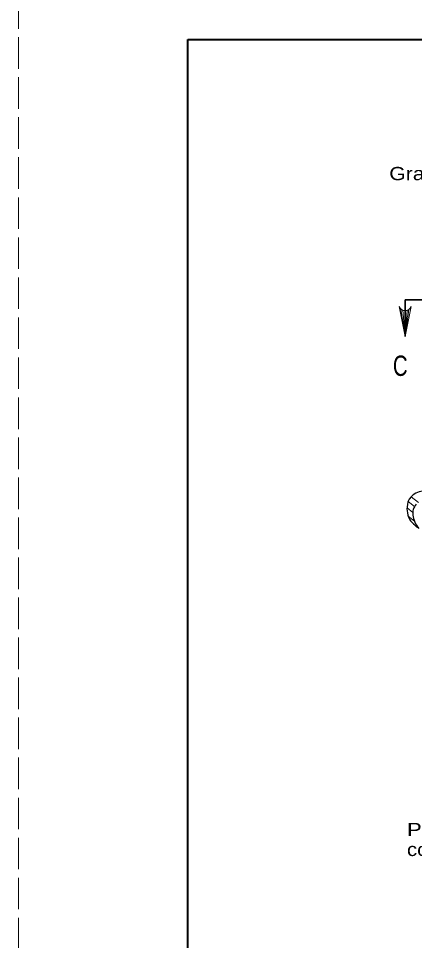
# Model space of a CAD drawing. Extents: x -410.5 to -376.5, y 1617.6 to 1661.6.
# Drawn here: x -410.45 to -405.78, y 1628.44 to 1639.31 of the extents above; entities that cross this region are included whole.
import ezdxf
from ezdxf.enums import TextEntityAlignment as Align

# ---------------------------------------------------------------- set-up
doc = ezdxf.new("R2010")
doc.units = 0
doc.header["$LTSCALE"] = 0.062
doc.linetypes.add('LONG_DASHED', pattern=[7.5, 6, -1.5])
doc.layers.add('1', color=7, linetype='Continuous', lineweight=13)

msp = doc.modelspace()

# ---------------------------------------------------------------- linework, layer by layer
at = {"layer": '1', "lineweight": 25}
msp.add_line((-408.45475, 1639.06183), (-376.95475, 1639.06183), dxfattribs=at)
at = {"layer": '1', "lineweight": 35}
for q in [(-400.21625, 1635.99217), (-405.888, 1635.5595)]:
    msp.add_line((-405.888, 1635.99217), q, dxfattribs=at)
at = {"layer": '1'}
for p, q in [((-405.93758, 1635.88375), (-405.888, 1635.5595)), ((-405.91683, 1635.8715), (-405.888, 1635.5595)), ((-405.84317, 1635.88), (-405.888, 1635.5595)), ((-405.86533, 1635.86908), (-405.888, 1635.5595)), ((-405.888, 1635.86583), (-405.888, 1635.5595)), ((-405.73167, 1633.60325), (-405.81658, 1633.67158)), ((-405.79842, 1633.48508), (-405.86592, 1633.53942)), ((-405.77842, 1633.55492), (-405.85283, 1633.61483)), ((-405.77775, 1633.38258), (-405.85083, 1633.44133)), ((-405.72758, 1633.29925), (-405.788, 1633.34783))]:
    msp.add_line(p, q, dxfattribs=at)
at = {"layer": '1', "linetype": 'LONG_DASHED'}
msp.add_lwpolyline([(-410.45475, 1617.56183), (-376.45475, 1617.56183), (-376.45475, 1639.56183), (-410.45475, 1639.56183)], close=True, dxfattribs=at)
at = {"layer": '1', "lineweight": 25}
msp.add_lwpolyline([(-376.95475, 1618.06183), (-408.45475, 1618.06183), (-408.45475, 1639.06183)], dxfattribs=at)
at = {"layer": '1', "lineweight": 40}
msp.add_lwpolyline([(-408.45475, 1639.06183), (-376.95475, 1639.06183), (-376.95475, 1618.06183), (-408.45475, 1618.06183)], close=True, dxfattribs=at)
msp.add_lwpolyline([(-408.45475, 1639.06183), (-376.95475, 1639.06183), (-376.95475, 1618.06183), (-408.45475, 1618.06183)], close=True, dxfattribs=at)
at = {"layer": '1'}
msp.add_lwpolyline([(-405.95883, 1635.9135), (-405.888, 1635.5595), (-405.81725, 1635.9135)], dxfattribs=at)
msp.add_arc((-405.88795, 1635.94207), 0.0764, 202.08605, 337.91218, dxfattribs=at)
at = {"layer": '1', "lineweight": 25}
for centre, major_axis, start_param, end_param in [((-405.63858, 1633.56188), (-0.22424, 0), 4.73259403, 6.19188747), ((-405.45475, 1633.53067), (-0.41142, 0), 6.13873376, 6.73878887), ((-405.58935, 1633.48317), (-0.20914, 0), 5.64753358, 6.45081579), ((-405.40132, 1633.4797), (0.39543, 0), 3.21902516, 3.74898168), ((-405.34174, 1633.65852), (0.59018, 0), 3.75535936, 4.00331106)]:
    msp.add_ellipse(centre, major_axis=major_axis, ratio=0.804622, start_param=start_param, end_param=end_param, dxfattribs=at)

# ---------------------------------------------------------------- texts
at = {"layer": '1'}
for s, width, p in [('Grate', 1.2, (-406.0755, 1637.40442)), ('Permissible', 1.25, (-405.866, 1629.66825)), ('const. joint', 1.15, (-405.866, 1629.43358))]:
    msp.add_text(s, height=0.156, dxfattribs=dict(at, width=width)).set_placement(p)
at = {"layer": '1', "width": 0.75}
msp.add_text('C', height=0.24, dxfattribs=at).set_placement((-405.94558, 1635.09608), align=Align.CENTER)

doc.saveas('drawing.dxf')
